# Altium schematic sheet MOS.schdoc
size 297 x 209 mm; Symbol: Drawing-Symbol_A4; Company: 嘉立创EDA; Version: V1.0; Page Size: A4; @Project Name: 西柚在学EtherCAT; @Update Date: 2026-07-29; @Create Date: 2026-07-29; Device: Drawing-Symbol_A4; @Board Name: HPM5E3YIVK1; @Page Name: P6; @Create Time: 01:19:19; @Page Count: 6; @Page No: 6; @Schematic Name: HPM5E3YIVK1; @Update Time: 01:19:19; @Assembly Variant: Basic; Border: 1; Title Block Position: 3; Size: A4; Width: 1170; Height: 825; Region Start: 1; X Region Count: 6; Y Region Count: 4; Blade Width: 10
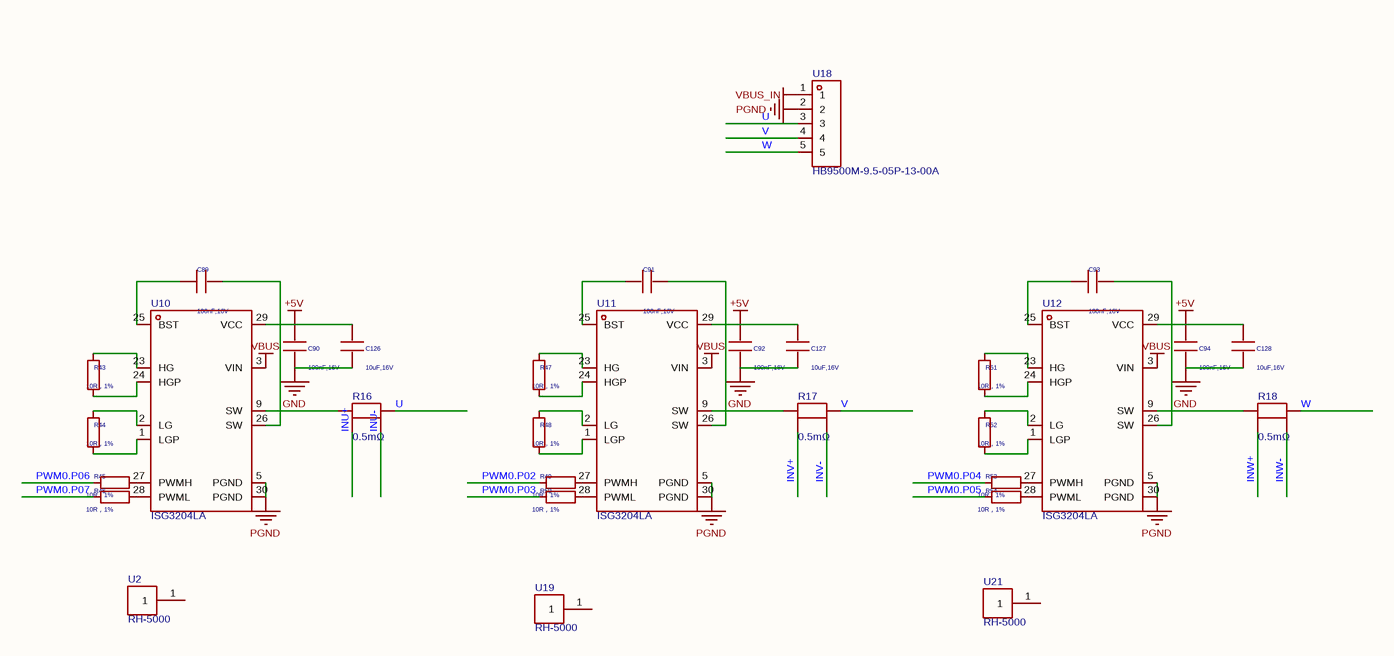
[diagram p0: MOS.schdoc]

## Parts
C89  value 100nF,16V  [03_HPM_Capacitance:C_0402_1005Metric]
C90  value 100nF,16V  [03_HPM_Capacitance:C_0402_1005Metric]
C91  value 100nF,16V  [03_HPM_Capacitance:C_0402_1005Metric]
C92  value 100nF,16V  [03_HPM_Capacitance:C_0402_1005Metric]
C93  value 100nF,16V  [03_HPM_Capacitance:C_0402_1005Metric]
C94  value 100nF,16V  [03_HPM_Capacitance:C_0402_1005Metric]
C126  value 10uF,16V  [03_HPM_Capacitance:C_0402_1005Metric]
C127  value 10uF,16V  [03_HPM_Capacitance:C_0402_1005Metric]
C128  value 10uF,16V  [03_HPM_Capacitance:C_0402_1005Metric]
R16  0.5mΩ  [RES-SMD_4P-L3.0-W3.8_HOBB1216]
R17  0.5mΩ  [RES-SMD_4P-L3.0-W3.8_HOBB1216]
R18  0.5mΩ  [RES-SMD_4P-L3.0-W3.8_HOBB1216]
R43  value 10R，1%  [02_HPM_Resistor:R_0402_1005Metric]
R44  value 10R，1%  [02_HPM_Resistor:R_0402_1005Metric]
R45  value 10R，1%  [02_HPM_Resistor:R_0402_1005Metric]
R46  value 10R，1%  [02_HPM_Resistor:R_0402_1005Metric]
R47  value 10R，1%  [02_HPM_Resistor:R_0402_1005Metric]
R48  value 10R，1%  [02_HPM_Resistor:R_0402_1005Metric]
R49  value 10R，1%  [02_HPM_Resistor:R_0402_1005Metric]
R50  value 10R，1%  [02_HPM_Resistor:R_0402_1005Metric]
R51  value 10R，1%  [02_HPM_Resistor:R_0402_1005Metric]
R52  value 10R，1%  [02_HPM_Resistor:R_0402_1005Metric]
R53  value 10R，1%  [02_HPM_Resistor:R_0402_1005Metric]
R54  value 10R，1%  [02_HPM_Resistor:R_0402_1005Metric]
U2  RH-5000  [TEST-TH_BD2.54-P1.4_RED]
U10  ISG3204LA  [LGA-25_L6.5-W5.0-P0.85-TL]
U11  ISG3204LA  [LGA-25_L6.5-W5.0-P0.85-TL]
U12  ISG3204LA  [LGA-25_L6.5-W5.0-P0.85-TL]
U18  HB9500M-9.5-05P-13-00A  [CONN-TH_HB9500M-9.5-5P]
U19  RH-5000  [TEST-TH_BD2.54-P1.4_RED]
U21  RH-5000  [TEST-TH_BD2.54-P1.4_RED]

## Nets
+5V: C90.1 C92.1 C94.1 C126.1 C127.1 C128.1 U10.29(VCC) U11.29(VCC) U12.29(VCC)
GND: C90.2 C92.2 C94.2 C126.2 C127.2 C128.2
PGND: U10.5(PGND) U10.30(PGND) U11.5(PGND) U11.30(PGND) U12.5(PGND) U12.30(PGND) U18.2
VBUS: U10.3(VIN) U11.3(VIN) U12.3(VIN)
VBUS_IN: U18.1
INU+: R16.4
INU-: R16.3
INV+: R17.4
INV-: R17.3
INW+: R18.4
INW-: R18.3
PWM0.P02: R49.2
PWM0.P03: R50.2
PWM0.P04: R53.2
PWM0.P05: R54.2
PWM0.P06: R45.2
PWM0.P07: R46.2
U: R16.1 U18.3
V: R17.1 U18.4
W: R18.1 U18.5
NetC89_1: C89.1 U10.26(SW)
NetC89_2: C89.2 U10.25(BST)
NetC91_1: C91.1 U11.26(SW)
NetC91_2: C91.2 U11.25(BST)
NetC93_1: C93.1 U12.26(SW)
NetC93_2: C93.2 U12.25(BST)
NetR16_2: R16.2 U10.9(SW)
NetR17_2: R17.2 U11.9(SW)
NetR18_2: R18.2 U12.9(SW)
NetR43_1: R43.1 U10.24(HGP)
NetR43_2: R43.2 U10.23(HG)
NetR44_1: R44.1 U10.1(LGP)
NetR44_2: R44.2 U10.2(LG)
NetR45_1: R45.1 U10.27(PWMH)
NetR46_1: R46.1 U10.28(PWML)
NetR47_1: R47.1 U11.24(HGP)
NetR47_2: R47.2 U11.23(HG)
NetR48_1: R48.1 U11.1(LGP)
NetR48_2: R48.2 U11.2(LG)
NetR49_1: R49.1 U11.27(PWMH)
NetR50_1: R50.1 U11.28(PWML)
NetR51_1: R51.1 U12.24(HGP)
NetR51_2: R51.2 U12.23(HG)
NetR52_1: R52.1 U12.1(LGP)
NetR52_2: R52.2 U12.2(LG)
NetR53_1: R53.1 U12.27(PWMH)
NetR54_1: R54.1 U12.28(PWML)

Not connected (* = marked no-connect by the designer): U2 1; U19 1; U21 1

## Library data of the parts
C89 = 电容0402: Model: CL05B104KO5NNNC; Company: SAMSUNG(三星); ki_keywords: cap capacitor; ki_description: 0402; ki_fp_filters: C_*; ID: $1I27; 3D Model: 222a10e09e6e477a9f85628e277082cb0819f05c4eef4c71ace90d822a990e87; 3D Model Transform: 39.37,19.685,19.685,0,0,0,0,0,0; AddInBom: yes; UniqueId: gge83_16; ModelName: C0402
C90 = 电容0402: Model: CL05B104KO5NNNC; Company: SAMSUNG(三星); ki_keywords: cap capacitor; ki_description: 0402; ki_fp_filters: C_*; ID: $1I27; 3D Model: 222a10e09e6e477a9f85628e277082cb0819f05c4eef4c71ace90d822a990e87; 3D Model Transform: 39.37,19.685,19.685,0,0,0,0,0,0; AddInBom: yes; UniqueId: gge83_17; ModelName: C0402
C91 = 电容0402: Model: CL05B104KO5NNNC; Company: SAMSUNG(三星); ki_keywords: cap capacitor; ki_description: 0402; ki_fp_filters: C_*; ID: $1I27; 3D Model: 222a10e09e6e477a9f85628e277082cb0819f05c4eef4c71ace90d822a990e87; 3D Model Transform: 39.37,19.685,19.685,0,0,0,0,0,0; AddInBom: yes; UniqueId: gge83_18; ModelName: C0402
C92 = 电容0402: Model: CL05B104KO5NNNC; Company: SAMSUNG(三星); ki_keywords: cap capacitor; ki_description: 0402; ki_fp_filters: C_*; ID: $1I27; 3D Model: 222a10e09e6e477a9f85628e277082cb0819f05c4eef4c71ace90d822a990e87; 3D Model Transform: 39.37,19.685,19.685,0,0,0,0,0,0; AddInBom: yes; UniqueId: gge83_19; ModelName: C0402
C93 = 电容0402: Model: CL05B104KO5NNNC; Company: SAMSUNG(三星); ki_keywords: cap capacitor; ki_description: 0402; ki_fp_filters: C_*; ID: $1I27; 3D Model: 222a10e09e6e477a9f85628e277082cb0819f05c4eef4c71ace90d822a990e87; 3D Model Transform: 39.37,19.685,19.685,0,0,0,0,0,0; AddInBom: yes; UniqueId: gge83_20; ModelName: C0402
C94 = 电容0402: Model: CL05B104KO5NNNC; Company: SAMSUNG(三星); ki_keywords: cap capacitor; ki_description: 0402; ki_fp_filters: C_*; ID: $1I27; 3D Model: 222a10e09e6e477a9f85628e277082cb0819f05c4eef4c71ace90d822a990e87; 3D Model Transform: 39.37,19.685,19.685,0,0,0,0,0,0; AddInBom: yes; UniqueId: gge83_21; ModelName: C0402
C126 = 电容0402: Model: CL05B104KO5NNNC; Company: SAMSUNG(三星); ki_keywords: cap capacitor; ki_description: 0402; ki_fp_filters: C_*; ID: $1I27; 3D Model: 222a10e09e6e477a9f85628e277082cb0819f05c4eef4c71ace90d822a990e87; 3D Model Transform: 39.37,19.685,19.685,0,0,0,0,0,0; AddInBom: yes; UniqueId: gge83_34; ModelName: C0402
C127 = 电容0402: Model: CL05B104KO5NNNC; Company: SAMSUNG(三星); ki_keywords: cap capacitor; ki_description: 0402; ki_fp_filters: C_*; ID: $1I27; 3D Model: 222a10e09e6e477a9f85628e277082cb0819f05c4eef4c71ace90d822a990e87; 3D Model Transform: 39.37,19.685,19.685,0,0,0,0,0,0; AddInBom: yes; UniqueId: gge83_35; ModelName: C0402
C128 = 电容0402: Model: CL05B104KO5NNNC; Company: SAMSUNG(三星); ki_keywords: cap capacitor; ki_description: 0402; ki_fp_filters: C_*; ID: $1I27; 3D Model: 222a10e09e6e477a9f85628e277082cb0819f05c4eef4c71ace90d822a990e87; 3D Model Transform: 39.37,19.685,19.685,0,0,0,0,0,0; AddInBom: yes; UniqueId: gge83_36; ModelName: C0402
R16-R18 = HoBB1216-5W-0.5mR-1%: 电阻类型:采样电阻;阻值:0.5mΩ;精度:±1%;功率:5W;温度系数:±50ppm/℃;安装方式:贴片;; Manufacturer: Milliohm(毫欧); AddInBom: yes; ModelId: 982d1509d24f4f009544b104e5e1a8a30819f05c4eef4c71ace90d822a990e87; ModelTransform: 118.5037,150.3934,0,180,0,0,0,-20.039,0; Tolerance: ±1%; Power(Watts): 5W
R43 = 电阻0402: Model: 0402WGF1002TCE; Company: UNI-ROYAL(厚声); ki_keywords: R res resistor; ki_description: Resistor; ki_fp_filters: R_*; ID: $3I57; 3D Model: 98c88bc2b9094f218f3a3e30a70127380819f05c4eef4c71ace90d822a990e87; 3D Model Transform: 39.37,19.685,14.173200563192367,0,0,0,0,0,0; AddInBom: yes; UniqueId: 469542c170a520e3_23; ModelName: R0402_L1.0-W0.5-H0.4
R44 = 电阻0402: Model: 0402WGF1002TCE; Company: UNI-ROYAL(厚声); ki_keywords: R res resistor; ki_description: Resistor; ki_fp_filters: R_*; ID: $3I57; 3D Model: 98c88bc2b9094f218f3a3e30a70127380819f05c4eef4c71ace90d822a990e87; 3D Model Transform: 39.37,19.685,14.173200563192367,0,0,0,0,0,0; AddInBom: yes; UniqueId: 469542c170a520e3_24; ModelName: R0402_L1.0-W0.5-H0.4
R45 = 电阻0402: Model: 0402WGF1002TCE; Company: UNI-ROYAL(厚声); ki_keywords: R res resistor; ki_description: Resistor; ki_fp_filters: R_*; ID: $3I57; 3D Model: 98c88bc2b9094f218f3a3e30a70127380819f05c4eef4c71ace90d822a990e87; 3D Model Transform: 39.37,19.685,14.173200563192367,0,0,0,0,0,0; AddInBom: yes; UniqueId: 469542c170a520e3_25; ModelName: R0402_L1.0-W0.5-H0.4
R46 = 电阻0402: Model: 0402WGF1002TCE; Company: UNI-ROYAL(厚声); ki_keywords: R res resistor; ki_description: Resistor; ki_fp_filters: R_*; ID: $3I57; 3D Model: 98c88bc2b9094f218f3a3e30a70127380819f05c4eef4c71ace90d822a990e87; 3D Model Transform: 39.37,19.685,14.173200563192367,0,0,0,0,0,0; AddInBom: yes; UniqueId: 469542c170a520e3_26; ModelName: R0402_L1.0-W0.5-H0.4
R47 = 电阻0402: Model: 0402WGF1002TCE; Company: UNI-ROYAL(厚声); ki_keywords: R res resistor; ki_description: Resistor; ki_fp_filters: R_*; ID: $3I57; 3D Model: 98c88bc2b9094f218f3a3e30a70127380819f05c4eef4c71ace90d822a990e87; 3D Model Transform: 39.37,19.685,14.173200563192367,0,0,0,0,0,0; AddInBom: yes; UniqueId: 469542c170a520e3_27; ModelName: R0402_L1.0-W0.5-H0.4
R48 = 电阻0402: Model: 0402WGF1002TCE; Company: UNI-ROYAL(厚声); ki_keywords: R res resistor; ki_description: Resistor; ki_fp_filters: R_*; ID: $3I57; 3D Model: 98c88bc2b9094f218f3a3e30a70127380819f05c4eef4c71ace90d822a990e87; 3D Model Transform: 39.37,19.685,14.173200563192367,0,0,0,0,0,0; AddInBom: yes; UniqueId: 469542c170a520e3_28; ModelName: R0402_L1.0-W0.5-H0.4
R49 = 电阻0402: Model: 0402WGF1002TCE; Company: UNI-ROYAL(厚声); ki_keywords: R res resistor; ki_description: Resistor; ki_fp_filters: R_*; ID: $3I57; 3D Model: 98c88bc2b9094f218f3a3e30a70127380819f05c4eef4c71ace90d822a990e87; 3D Model Transform: 39.37,19.685,14.173200563192367,0,0,0,0,0,0; AddInBom: yes; UniqueId: 469542c170a520e3_29; ModelName: R0402_L1.0-W0.5-H0.4
R50 = 电阻0402: Model: 0402WGF1002TCE; Company: UNI-ROYAL(厚声); ki_keywords: R res resistor; ki_description: Resistor; ki_fp_filters: R_*; ID: $3I57; 3D Model: 98c88bc2b9094f218f3a3e30a70127380819f05c4eef4c71ace90d822a990e87; 3D Model Transform: 39.37,19.685,14.173200563192367,0,0,0,0,0,0; AddInBom: yes; UniqueId: 469542c170a520e3_30; ModelName: R0402_L1.0-W0.5-H0.4
R51 = 电阻0402: Model: 0402WGF1002TCE; Company: UNI-ROYAL(厚声); ki_keywords: R res resistor; ki_description: Resistor; ki_fp_filters: R_*; ID: $3I57; 3D Model: 98c88bc2b9094f218f3a3e30a70127380819f05c4eef4c71ace90d822a990e87; 3D Model Transform: 39.37,19.685,14.173200563192367,0,0,0,0,0,0; AddInBom: yes; UniqueId: 469542c170a520e3_31; ModelName: R0402_L1.0-W0.5-H0.4
R52 = 电阻0402: Model: 0402WGF1002TCE; Company: UNI-ROYAL(厚声); ki_keywords: R res resistor; ki_description: Resistor; ki_fp_filters: R_*; ID: $3I57; 3D Model: 98c88bc2b9094f218f3a3e30a70127380819f05c4eef4c71ace90d822a990e87; 3D Model Transform: 39.37,19.685,14.173200563192367,0,0,0,0,0,0; AddInBom: yes; UniqueId: 469542c170a520e3_32; ModelName: R0402_L1.0-W0.5-H0.4
R53 = 电阻0402: Model: 0402WGF1002TCE; Company: UNI-ROYAL(厚声); ki_keywords: R res resistor; ki_description: Resistor; ki_fp_filters: R_*; ID: $3I57; 3D Model: 98c88bc2b9094f218f3a3e30a70127380819f05c4eef4c71ace90d822a990e87; 3D Model Transform: 39.37,19.685,14.173200563192367,0,0,0,0,0,0; AddInBom: yes; UniqueId: 469542c170a520e3_33; ModelName: R0402_L1.0-W0.5-H0.4
R54 = 电阻0402: Model: 0402WGF1002TCE; Company: UNI-ROYAL(厚声); ki_keywords: R res resistor; ki_description: Resistor; ki_fp_filters: R_*; ID: $3I57; 3D Model: 98c88bc2b9094f218f3a3e30a70127380819f05c4eef4c71ace90d822a990e87; 3D Model Transform: 39.37,19.685,14.173200563192367,0,0,0,0,0,0; AddInBom: yes; UniqueId: 469542c170a520e3_34; ModelName: R0402_L1.0-W0.5-H0.4
U2 U19 U21 = RH-5000: Manufacturer: 荣和; AddInBom: yes; ModelId: 3ee70e2a8afb47659abb73033ae4c5d50819f05c4eef4c71ace90d822a990e87; ModelTransform: 98.425,98.79098,0,0,0,0,0,0,-125.984; Connector Type: 插针型(穿板); Plastic Color: 红色; Board Space (Diameter φ/ Length x Width): 2.5mm
U10 = ISG3204LA: Manufacturer: Innoscience(英诺赛科); AddInBom: yes; UniqueId: gge1093; ID: $6I2; ModelId: 827b3749c74c40448110c099cfa9c3000819f05c4eef4c71ace90d822a990e87; ModelName: LGA-30_L6.5-W5.0-P0.85-TL_ISG3206LA; ModelTransform: 196.85,255.90499999999997,44.88179980346933,0,0,0,0,0,0
U11 = ISG3204LA: Manufacturer: Innoscience(英诺赛科); AddInBom: yes; UniqueId: gge1088; ID: $6I2; ModelId: 827b3749c74c40448110c099cfa9c3000819f05c4eef4c71ace90d822a990e87; ModelName: LGA-30_L6.5-W5.0-P0.85-TL_ISG3206LA; ModelTransform: 196.85,255.90499999999997,44.88179980346933,0,0,0,0,0,0
U12 = ISG3204LA: Manufacturer: Innoscience(英诺赛科); AddInBom: yes; UniqueId: gge1089; ID: $6I2; ModelId: 827b3749c74c40448110c099cfa9c3000819f05c4eef4c71ace90d822a990e87; ModelName: LGA-30_L6.5-W5.0-P0.85-TL_ISG3206LA; ModelTransform: 196.85,255.90499999999997,44.88179980346933,0,0,0,0,0,0
U18 = HB9500M-9.5-05P-13-00A: 隔板类型:带盖板;间距:9.5mm;结构:1x5P;安装方式:直插;引脚位置:边脚;排数:1;每排PIN数:5;额定电流:32A;额定电压:750V;线规 - AWG:12~22;线规 - 平方毫米:4;工作温度:-40℃~+105℃;颜色:黑色;; Manufacturer: KANGNEX(康奈克斯电气); Symbol: HB9500M-9.5-5P; AddInBom: yes; ModelId: 11f48a5dea614f579239e1868bc69a220819f05c4eef4c71ace90d822a990e87; ModelTransform: 1929.13,629.92,0,0,0,0,0,-159.764,-204.724; Barrier Type: 带盖板; Pitch: 9.5mm; Number of Positions or Pins: 1x5P; Pin Location: 边脚; Number of PINs Per Row: 5; Current Rating: 32A; Voltage Rating (Max): 750V; Wire Gauge - AWG: 12~22; Wire Gauge - mm2: 4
